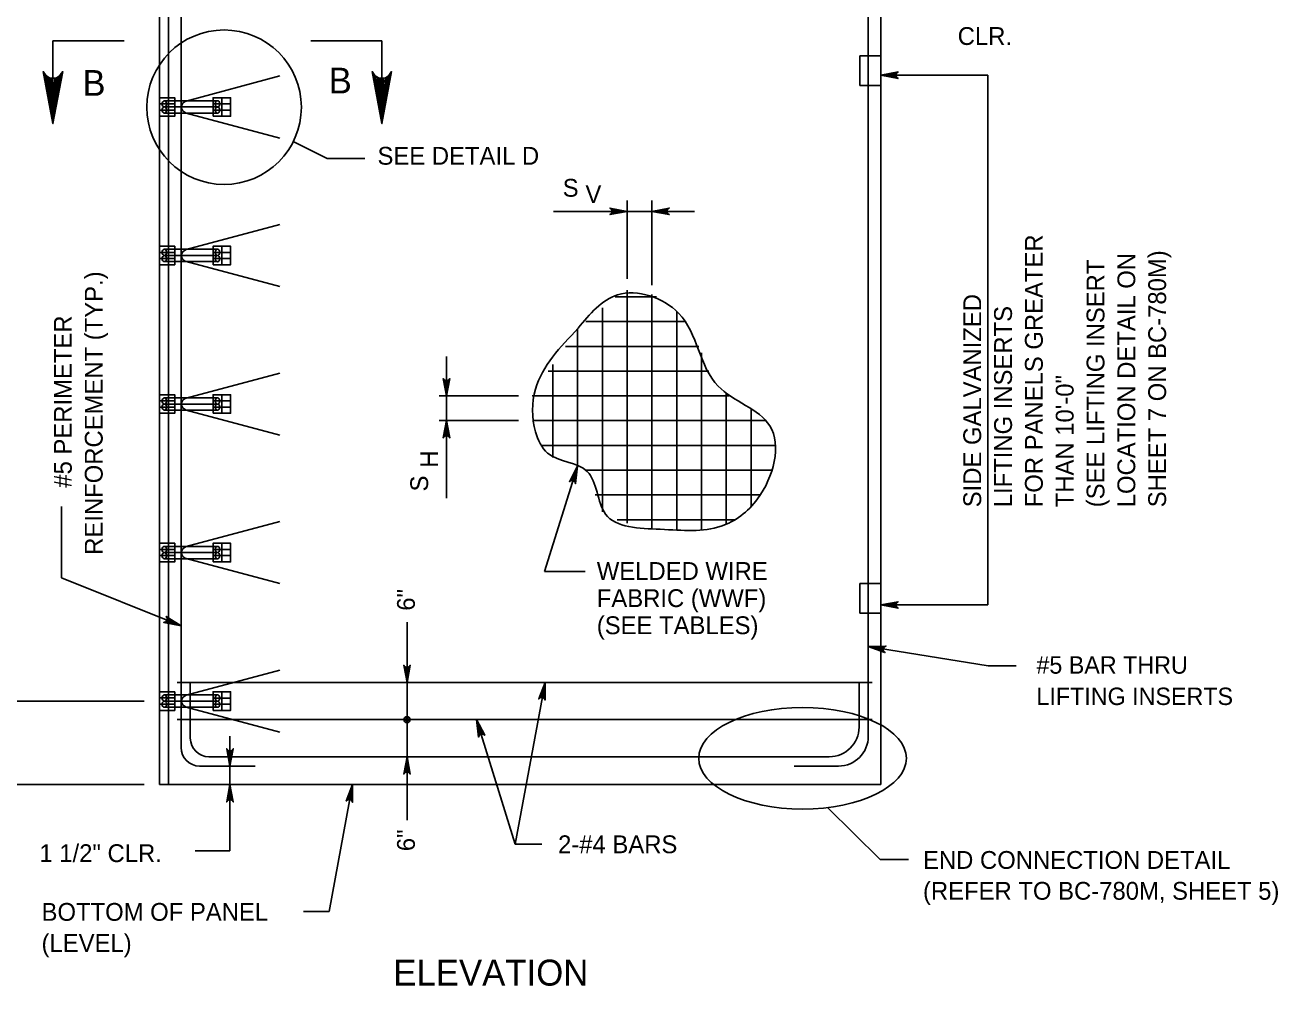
# Model space of a CAD drawing. Extents: x 3385 to 6532, y -616 to 1166.
# Drawn here: x 5875.8 to 6091.7, y 266.6 to 432.2 of the extents above; entities that cross this region are included whole.
import ezdxf

# ---------------------------------------------------------------- set-up
doc = ezdxf.new("R2010")
doc.units = 0
doc.layers.add('1', color=7, linetype='Continuous')

msp = doc.modelspace()

# ---------------------------------------------------------------- linework, layer by layer
at = {"layer": '1'}
for p, q in [((5899.03, 456.51), (5899.03, 301.32)), ((5900.59, 456.51), (5900.59, 301.32)), ((6023.26, 456.51), (6023.26, 301.32)), ((5902.72, 450.11), (5902.72, 307.72)), ((6021.13, 448.19), (6021.13, 309.64)), ((5892.92, 429.52), (5880.66, 429.52)), ((5880.66, 429.52), (5880.66, 415.25)), ((5925.07, 429.52), (5937.33, 429.52)), ((5937.33, 429.52), (5937.33, 415.25)), ((6023.26, 426.95), (6019.68, 426.95)), ((6019.68, 421.83), (6019.68, 426.95)), ((5919.73, 423.45), (5903.62, 419.13)), ((6041.73, 423.58), (6023.26, 423.58)), ((6041.73, 423.58), (6041.73, 332.29)), ((6023.26, 421.83), (6019.68, 421.83)), ((5909, 419.18), (5899.85, 419.18)), ((5909.76, 417.58), (5909.76, 419.71)), ((5909, 418.11), (5899.85, 418.11)), ((5909, 417.05), (5899.85, 417.05)), ((5903.62, 417.07), (5919.73, 412.75)), ((5909.76, 417.58), (5909.76, 416.51)), ((5927.9, 409.23), (5922.05, 412.14)), ((5934.38, 409.23), (5927.9, 409.23)), ((5979.59, 388.47), (5979.59, 402)), ((5983.85, 387.38), (5983.85, 402)), ((5966.92, 400.12), (5991.16, 400.12)), ((5919.73, 397.85), (5903.62, 393.53)), ((5909, 393.58), (5899.85, 393.58)), ((5909.76, 391.98), (5909.76, 394.11)), ((5909, 392.51), (5899.85, 392.51)), ((5909, 391.45), (5899.85, 391.45)), ((5903.62, 391.47), (5919.73, 387.16)), ((5909.76, 391.98), (5909.76, 390.91)), ((5979.59, 386.53), (5979.59, 346.37)), ((5984.64, 385.38), (5977.53, 385.38)), ((5983.85, 385.78), (5983.85, 345.49)), ((5975.32, 383.51), (5975.32, 348.34)), ((5988.12, 382.88), (5988.12, 345.11)), ((5989.71, 381.12), (5972.49, 381.12)), ((5971.05, 379.85), (5971.05, 356.21)), ((5991.94, 376.85), (5968.95, 376.85)), ((5992.38, 375.72), (5992.38, 345.19)), ((5948.45, 350.69), (5948.45, 375.09)), ((5966.79, 373.75), (5966.79, 357.7)), ((5919.73, 372.25), (5903.62, 367.93)), ((5993.67, 372.58), (5965.97, 372.58)), ((5909, 367.98), (5899.85, 367.98)), ((5909.76, 366.38), (5909.76, 368.51)), ((5947.22, 368.32), (5960.86, 368.32)), ((5997.14, 368.32), (5963.23, 368.32)), ((5996.65, 368.67), (5996.65, 346.17)), ((5909, 366.91), (5899.85, 366.91)), ((5909, 365.85), (5899.85, 365.85)), ((5903.62, 365.87), (5919.73, 361.56)), ((5909.76, 366.38), (5909.76, 365.31)), ((6000.92, 366.01), (6000.92, 349.28)), ((5947.22, 364.05), (5960.86, 364.05)), ((6003.48, 364.05), (5963.28, 364.05)), ((6005.15, 359.78), (5964.86, 359.78)), ((5971.05, 356.21), (5965.34, 338.05)), ((6004.63, 355.52), (5972.43, 355.52)), ((6002.59, 351.25), (5974.09, 351.25)), ((5882.15, 349.23), (5882.15, 336.95)), ((5919.73, 346.65), (5903.62, 342.33)), ((5998.22, 346.98), (5977.85, 346.98)), ((5909, 342.38), (5899.85, 342.38)), ((5909, 341.31), (5899.85, 341.31)), ((5909.76, 340.78), (5909.76, 342.91)), ((5909, 340.25), (5899.85, 340.25)), ((5903.62, 340.27), (5919.73, 335.96)), ((5909.76, 340.78), (5909.76, 339.71)), ((5882.15, 336.95), (5902.72, 328.68)), ((5965.34, 338.05), (5972.37, 338.05)), ((6023.26, 336), (6019.68, 336)), ((6019.68, 330.88), (6019.68, 336)), ((6023.26, 330.88), (6019.68, 330.88)), ((6041.73, 332.29), (6023.26, 332.29)), ((5941.66, 329.32), (5941.66, 295.19)), ((6041.78, 321.81), (6021.13, 325.11)), ((6046.59, 321.81), (6041.78, 321.81)), ((5919.73, 321.05), (5903.62, 316.73)), ((5902.07, 318.92), (6021.78, 318.92)), ((5904.32, 309.32), (5904.32, 318.92)), ((5909.76, 315.18), (5909.76, 317.32)), ((5960.28, 291.04), (5965.45, 318.92)), ((6019.53, 311.24), (6019.53, 318.92)), ((5870.36, 315.72), (5896.39, 315.72)), ((5909, 316.78), (5899.85, 316.78)), ((5909, 315.71), (5899.85, 315.71)), ((5909.76, 315.18), (5909.76, 314.11)), ((5909, 314.65), (5899.85, 314.65)), ((5903.62, 314.67), (5919.73, 310.36)), ((5902.07, 312.52), (6021.78, 312.52)), ((5960.28, 291.04), (5953.63, 312.52)), ((5911.15, 309.66), (5911.15, 289.91)), ((5905.92, 304.52), (5915.52, 304.52)), ((5907.52, 306.12), (6014.41, 306.12)), ((6008.33, 304.52), (6016.01, 304.52)), ((5896.39, 301.32), (5826.79, 301.32)), ((5899.03, 301.32), (6023.26, 301.32)), ((5928.22, 279.47), (5932.27, 301.32)), ((6014.11, 297.37), (6023.15, 288.4)), ((5905.13, 289.91), (5911.15, 289.91)), ((5960.28, 291.04), (5964.91, 291.04)), ((6028.06, 288.4), (6023.15, 288.4)), ((5928.22, 279.47), (5923.83, 279.47))]:
    msp.add_line(p, q, dxfattribs=at)
for points in [[(5880.66, 415.25), (5882.33, 424.2), (5882.09, 423.85), (5881.86, 423.51), (5881.56, 423.33), (5881.26, 423.15), (5880.96, 423.1), (5880.66, 423.05), (5880.36, 423.1), (5880.06, 423.15), (5879.76, 423.33), (5879.46, 423.51), (5879.22, 423.85), (5878.98, 424.2), (5880.66, 415.25), (5879.22, 423.85), (5879.46, 423.51), (5880.66, 415.25), (5879.76, 423.33), (5880.06, 423.15), (5880.66, 415.25), (5880.36, 423.1), (5880.66, 423.05), (5880.66, 415.25), (5880.96, 423.1), (5881.26, 423.15), (5880.66, 415.25), (5881.56, 423.33), (5881.86, 423.51), (5880.66, 415.25), (5882.09, 423.85)], [(5937.33, 415.25), (5935.66, 424.2), (5935.89, 423.85), (5936.13, 423.51), (5936.43, 423.33), (5936.73, 423.15), (5937.03, 423.1), (5937.33, 423.05), (5937.63, 423.1), (5937.93, 423.15), (5938.23, 423.33), (5938.53, 423.51), (5938.77, 423.85), (5939.01, 424.2), (5937.33, 415.25), (5938.77, 423.85), (5938.53, 423.51), (5937.33, 415.25), (5938.23, 423.33), (5937.93, 423.15), (5937.33, 415.25), (5937.63, 423.1), (5937.33, 423.05), (5937.33, 415.25), (5937.03, 423.1), (5936.73, 423.15), (5937.33, 415.25), (5936.43, 423.33), (5936.13, 423.51), (5937.33, 415.25), (5935.89, 423.85)], [(6023.26, 423.58), (6026.25, 423.02), (6026.02, 423.18), (6025.9, 423.38), (6025.86, 423.58), (6025.9, 423.78), (6026.02, 423.98), (6026.25, 424.14), (6023.26, 423.58), (6026.02, 423.98), (6025.9, 423.78), (6023.26, 423.58), (6025.86, 423.58), (6025.9, 423.38), (6023.26, 423.58), (6026.02, 423.18)], [(5979.59, 400.12), (5976.6, 399.56), (5976.72, 399.64), (5976.83, 399.72), (5976.89, 399.82), (5976.95, 399.92), (5976.97, 400.02), (5976.99, 400.12), (5976.97, 400.22), (5976.95, 400.32), (5976.89, 400.42), (5976.83, 400.52), (5976.72, 400.6), (5976.6, 400.68), (5979.59, 400.12), (5976.72, 400.6), (5976.83, 400.52), (5979.59, 400.12), (5976.89, 400.42), (5976.95, 400.32), (5979.59, 400.12), (5976.97, 400.22), (5976.99, 400.12), (5979.59, 400.12), (5976.97, 400.02), (5976.95, 399.92), (5979.59, 400.12), (5976.89, 399.82), (5976.83, 399.72), (5979.59, 400.12), (5976.72, 399.64)], [(5983.85, 400.12), (5986.83, 400.68), (5986.72, 400.6), (5986.6, 400.52), (5986.55, 400.42), (5986.49, 400.32), (5986.47, 400.22), (5986.45, 400.12), (5986.47, 400.02), (5986.49, 399.92), (5986.55, 399.82), (5986.6, 399.72), (5986.72, 399.64), (5986.83, 399.56), (5983.85, 400.12), (5986.72, 399.64), (5986.6, 399.72), (5983.85, 400.12), (5986.55, 399.82), (5986.49, 399.92), (5983.85, 400.12), (5986.47, 400.02), (5986.45, 400.12), (5983.85, 400.12), (5986.47, 400.22), (5986.49, 400.32), (5983.85, 400.12), (5986.55, 400.42), (5986.6, 400.52), (5983.85, 400.12), (5986.72, 400.6)], [(5948.45, 368.32), (5947.89, 371.3), (5947.97, 371.18), (5948.05, 371.07), (5948.15, 371.01), (5948.25, 370.95), (5948.35, 370.93), (5948.45, 370.92), (5948.55, 370.93), (5948.65, 370.95), (5948.75, 371.01), (5948.85, 371.07), (5948.93, 371.18), (5949.01, 371.3), (5948.45, 368.32), (5948.93, 371.18), (5948.85, 371.07), (5948.45, 368.32), (5948.75, 371.01), (5948.65, 370.95), (5948.45, 368.32), (5948.55, 370.93), (5948.45, 370.92), (5948.45, 368.32), (5948.35, 370.93), (5948.25, 370.95), (5948.45, 368.32), (5948.15, 371.01), (5948.05, 371.07), (5948.45, 368.32), (5947.97, 371.18)], [(5948.45, 364.05), (5949.01, 361.07), (5948.93, 361.18), (5948.85, 361.3), (5948.75, 361.36), (5948.65, 361.42), (5948.55, 361.43), (5948.45, 361.45), (5948.35, 361.43), (5948.25, 361.42), (5948.15, 361.36), (5948.05, 361.3), (5947.97, 361.18), (5947.89, 361.07), (5948.45, 364.05), (5947.97, 361.18), (5948.05, 361.3), (5948.45, 364.05), (5948.15, 361.36), (5948.25, 361.42), (5948.45, 364.05), (5948.35, 361.43), (5948.45, 361.45), (5948.45, 364.05), (5948.55, 361.43), (5948.65, 361.42), (5948.45, 364.05), (5948.75, 361.36), (5948.85, 361.3), (5948.45, 364.05), (5948.93, 361.18)], [(5971.05, 356.21), (5970.69, 353.2), (5970.65, 353.33), (5970.61, 353.47), (5970.53, 353.55), (5970.45, 353.64), (5970.36, 353.69), (5970.27, 353.73), (5970.17, 353.75), (5970.07, 353.76), (5969.96, 353.73), (5969.84, 353.71), (5969.73, 353.62), (5969.62, 353.53), (5971.05, 356.21), (5969.73, 353.62), (5969.84, 353.71), (5971.05, 356.21), (5969.96, 353.73), (5970.07, 353.76), (5971.05, 356.21), (5970.17, 353.75), (5970.27, 353.73), (5971.05, 356.21), (5970.36, 353.69), (5970.45, 353.64), (5971.05, 356.21), (5970.53, 353.55), (5970.61, 353.47), (5971.05, 356.21), (5970.65, 353.33)], [(6023.26, 332.29), (6026.25, 331.73), (6026.02, 331.89), (6025.9, 332.09), (6025.86, 332.29), (6025.9, 332.49), (6026.02, 332.69), (6026.25, 332.85), (6023.26, 332.29), (6026.02, 332.69), (6025.9, 332.49), (6023.26, 332.29), (6025.86, 332.29), (6025.9, 332.09), (6023.26, 332.29), (6026.02, 331.89)], [(5902.72, 328.68), (5899.75, 329.28), (5899.88, 329.31), (5900.02, 329.34), (5900.11, 329.41), (5900.2, 329.48), (5900.26, 329.57), (5900.31, 329.65), (5900.33, 329.75), (5900.35, 329.85), (5900.33, 329.97), (5900.32, 330.08), (5900.24, 330.2), (5900.16, 330.32), (5902.72, 328.68), (5900.24, 330.2), (5900.32, 330.08), (5902.72, 328.68), (5900.33, 329.97), (5900.35, 329.85), (5902.72, 328.68), (5900.33, 329.75), (5900.31, 329.65), (5902.72, 328.68), (5900.26, 329.57), (5900.2, 329.48), (5902.72, 328.68), (5900.11, 329.41), (5900.02, 329.34), (5902.72, 328.68), (5899.88, 329.31)], [(6021.13, 325.11), (6024.16, 325.19), (6024.04, 325.13), (6023.91, 325.07), (6023.84, 324.98), (6023.76, 324.89), (6023.73, 324.8), (6023.7, 324.7), (6023.7, 324.6), (6023.7, 324.5), (6023.74, 324.39), (6023.79, 324.28), (6023.89, 324.19), (6023.99, 324.09), (6021.13, 325.11), (6023.89, 324.19), (6023.79, 324.28), (6021.13, 325.11), (6023.74, 324.39), (6023.7, 324.5), (6021.13, 325.11), (6023.7, 324.6), (6023.7, 324.7), (6021.13, 325.11), (6023.73, 324.8), (6023.76, 324.89), (6021.13, 325.11), (6023.84, 324.98), (6023.91, 325.07), (6021.13, 325.11), (6024.04, 325.13)], [(5941.66, 318.92), (5941.1, 321.9), (5941.18, 321.78), (5941.26, 321.67), (5941.36, 321.61), (5941.46, 321.55), (5941.56, 321.53), (5941.66, 321.52), (5941.76, 321.53), (5941.86, 321.55), (5941.96, 321.61), (5942.06, 321.67), (5942.14, 321.78), (5942.22, 321.9), (5941.66, 318.92), (5942.14, 321.78), (5942.06, 321.67), (5941.66, 318.92), (5941.96, 321.61), (5941.86, 321.55), (5941.66, 318.92), (5941.76, 321.53), (5941.66, 321.52), (5941.66, 318.92), (5941.56, 321.53), (5941.46, 321.55), (5941.66, 318.92), (5941.36, 321.61), (5941.26, 321.67), (5941.66, 318.92), (5941.18, 321.78)], [(5965.45, 318.92), (5965.45, 315.88), (5965.4, 316.01), (5965.34, 316.14), (5965.25, 316.21), (5965.16, 316.29), (5965.07, 316.32), (5964.97, 316.36), (5964.87, 316.36), (5964.77, 316.36), (5964.66, 316.32), (5964.55, 316.28), (5964.45, 316.18), (5964.35, 316.08), (5965.45, 318.92), (5964.45, 316.18), (5964.55, 316.28), (5965.45, 318.92), (5964.66, 316.32), (5964.77, 316.36), (5965.45, 318.92), (5964.87, 316.36), (5964.97, 316.36), (5965.45, 318.92), (5965.07, 316.32), (5965.16, 316.29), (5965.45, 318.92), (5965.25, 316.21), (5965.34, 316.14), (5965.45, 318.92), (5965.4, 316.01)], [(5953.63, 312.52), (5955.04, 309.83), (5954.93, 309.92), (5954.82, 310), (5954.71, 310.03), (5954.6, 310.06), (5954.5, 310.04), (5954.4, 310.03), (5954.31, 309.99), (5954.22, 309.94), (5954.14, 309.85), (5954.06, 309.77), (5954.02, 309.63), (5953.98, 309.5), (5953.63, 312.52), (5954.02, 309.63), (5954.06, 309.77), (5953.63, 312.52), (5954.14, 309.85), (5954.22, 309.94), (5953.63, 312.52), (5954.31, 309.99), (5954.4, 310.03), (5953.63, 312.52), (5954.5, 310.04), (5954.6, 310.06), (5953.63, 312.52), (5954.71, 310.03), (5954.82, 310), (5953.63, 312.52), (5954.93, 309.92)], [(5911.15, 304.52), (5910.59, 307.5), (5910.67, 307.38), (5910.75, 307.27), (5910.85, 307.21), (5910.95, 307.15), (5911.05, 307.13), (5911.15, 307.12), (5911.25, 307.13), (5911.35, 307.15), (5911.45, 307.21), (5911.55, 307.27), (5911.63, 307.38), (5911.71, 307.5), (5911.15, 304.52), (5911.63, 307.38), (5911.55, 307.27), (5911.15, 304.52), (5911.45, 307.21), (5911.35, 307.15), (5911.15, 304.52), (5911.25, 307.13), (5911.15, 307.12), (5911.15, 304.52), (5911.05, 307.13), (5910.95, 307.15), (5911.15, 304.52), (5910.85, 307.21), (5910.75, 307.27), (5911.15, 304.52), (5910.67, 307.38)], [(5941.66, 306.12), (5942.22, 303.13), (5942.14, 303.25), (5942.06, 303.36), (5941.96, 303.42), (5941.86, 303.48), (5941.76, 303.5), (5941.66, 303.52), (5941.56, 303.5), (5941.46, 303.48), (5941.36, 303.42), (5941.26, 303.36), (5941.18, 303.25), (5941.1, 303.13), (5941.66, 306.12), (5941.18, 303.25), (5941.26, 303.36), (5941.66, 306.12), (5941.36, 303.42), (5941.46, 303.48), (5941.66, 306.12), (5941.56, 303.5), (5941.66, 303.52), (5941.66, 306.12), (5941.76, 303.5), (5941.86, 303.48), (5941.66, 306.12), (5941.96, 303.42), (5942.06, 303.36), (5941.66, 306.12), (5942.14, 303.25)], [(5911.15, 301.32), (5911.71, 298.33), (5911.63, 298.45), (5911.55, 298.56), (5911.45, 298.62), (5911.35, 298.68), (5911.25, 298.7), (5911.15, 298.72), (5911.05, 298.7), (5910.95, 298.68), (5910.85, 298.62), (5910.75, 298.56), (5910.67, 298.45), (5910.59, 298.33), (5911.15, 301.32), (5910.67, 298.45), (5910.75, 298.56), (5911.15, 301.32), (5910.85, 298.62), (5910.95, 298.68), (5911.15, 301.32), (5911.05, 298.7), (5911.15, 298.72), (5911.15, 301.32), (5911.25, 298.7), (5911.35, 298.68), (5911.15, 301.32), (5911.45, 298.62), (5911.55, 298.56), (5911.15, 301.32), (5911.63, 298.45)], [(5932.27, 301.32), (5932.28, 298.28), (5932.22, 298.41), (5932.16, 298.54), (5932.07, 298.61), (5931.99, 298.69), (5931.89, 298.72), (5931.8, 298.76), (5931.7, 298.76), (5931.59, 298.76), (5931.48, 298.72), (5931.38, 298.68), (5931.28, 298.58), (5931.18, 298.48), (5932.27, 301.32), (5931.28, 298.58), (5931.38, 298.68), (5932.27, 301.32), (5931.48, 298.72), (5931.59, 298.76), (5932.27, 301.32), (5931.7, 298.76), (5931.8, 298.76), (5932.27, 301.32), (5931.89, 298.72), (5931.99, 298.69), (5932.27, 301.32), (5932.07, 298.61), (5932.16, 298.54), (5932.27, 301.32), (5932.22, 298.41)]]:
    msp.add_lwpolyline(points, dxfattribs=at)
for points in [[(5899.03, 417.58), (5901.65, 417.58), (5901.65, 419.71), (5899.03, 419.71)], [(5908.25, 417.58), (5911.27, 417.58), (5911.27, 419.71), (5908.25, 419.71)], [(5899.03, 416.51), (5901.65, 416.51), (5901.65, 418.64), (5899.03, 418.64)], [(5908.25, 416.51), (5911.27, 416.51), (5911.27, 418.64), (5908.25, 418.64)], [(5899.03, 391.98), (5901.65, 391.98), (5901.65, 394.11), (5899.03, 394.11)], [(5899.03, 390.91), (5901.65, 390.91), (5901.65, 393.05), (5899.03, 393.05)], [(5908.25, 391.98), (5911.27, 391.98), (5911.27, 394.11), (5908.25, 394.11)], [(5908.25, 390.91), (5911.27, 390.91), (5911.27, 393.04), (5908.25, 393.04)], [(5899.03, 366.38), (5901.65, 366.38), (5901.65, 368.51), (5899.03, 368.51)], [(5899.03, 365.31), (5901.65, 365.31), (5901.65, 367.45), (5899.03, 367.45)], [(5908.25, 366.38), (5911.27, 366.38), (5911.27, 368.51), (5908.25, 368.51)], [(5908.25, 365.31), (5911.27, 365.31), (5911.27, 367.44), (5908.25, 367.44)], [(5899.03, 340.78), (5901.65, 340.78), (5901.65, 342.91), (5899.03, 342.91)], [(5899.03, 339.71), (5901.65, 339.71), (5901.65, 341.85), (5899.03, 341.85)], [(5908.25, 340.78), (5911.27, 340.78), (5911.27, 342.91), (5908.25, 342.91)], [(5908.25, 339.71), (5911.27, 339.71), (5911.27, 341.84), (5908.25, 341.84)], [(5899.03, 315.18), (5901.65, 315.18), (5901.65, 317.31), (5899.03, 317.31)], [(5908.25, 315.18), (5911.27, 315.18), (5911.27, 317.32), (5908.25, 317.32)], [(5899.03, 314.11), (5901.65, 314.11), (5901.65, 316.25), (5899.03, 316.25)], [(5908.25, 314.11), (5911.27, 314.11), (5911.27, 316.24), (5908.25, 316.24)]]:
    msp.add_lwpolyline(points, close=True, dxfattribs=at)
for centre, radius in [((5910.14, 418.07), 13.31), ((5941.66, 312.52), 0.533), ((5941.66, 312.52), 0.267)]:
    msp.add_circle(centre, radius, dxfattribs=at)
for centre, radius, start, end in [((5903.89, 418.1), 1.07, 105, 255), ((5903.89, 392.5), 1.07, 105, 255), ((5903.89, 366.9), 1.07, 105, 255), ((5903.89, 341.3), 1.07, 105, 255), ((5903.89, 315.7), 1.07, 105, 255), ((6014.41, 311.24), 5.12, 270, 360), ((5907.52, 309.32), 3.2, 180, 270), ((6016.01, 309.64), 5.12, 270, 360), ((5905.92, 307.72), 3.2, 180, 270)]:
    msp.add_arc(centre, radius, start, end, dxfattribs=at)
for centre, major_axis, ratio in [((5899.85, 418.64), (0, 0.534), 0.741868), ((5909, 418.65), (0, 0.534), 0.741868), ((5899.85, 417.58), (0, 0.531), 0.745444), ((5909, 417.57), (0, 0.534), 0.741868), ((5899.85, 393.04), (0, 0.534), 0.741868), ((5909, 393.05), (0, 0.534), 0.741868), ((5899.85, 391.98), (0, 0.531), 0.745444), ((5909, 391.98), (0, 0.534), 0.741868), ((5899.85, 367.44), (0, 0.534), 0.741868), ((5909, 367.45), (0, 0.534), 0.741868), ((5899.85, 366.38), (0, 0.531), 0.745444), ((5909, 366.38), (0, 0.534), 0.741868), ((5899.85, 341.84), (0, 0.534), 0.741868), ((5899.85, 340.78), (0, 0.531), 0.745444), ((5909, 341.85), (0, 0.534), 0.741868), ((5909, 340.78), (0, 0.534), 0.741868), ((5899.85, 316.24), (0, 0.534), 0.741868), ((5899.85, 315.18), (0, 0.531), 0.745444), ((5909, 316.25), (0, 0.534), 0.741868), ((5909, 315.18), (0, 0.534), 0.741868), ((6009.8, 305.86), (17.89, 0), 0.489021)]:
    msp.add_ellipse(centre, major_axis=major_axis, ratio=ratio, dxfattribs=at)
msp.add_spline([(5971.13, 379.96), (5963.79, 369.47), (5963.79, 362.12), (5965.88, 358.45), (5972.7, 355.3), (5975.85, 347.95), (5985.28, 345.33), (5995.77, 345.85), (6002.06, 350.58), (6004.16, 363.17), (5995.25, 369.99), (5988.43, 382.59), (5977.94, 385.73), (5971.13, 379.96)], degree=3, dxfattribs=at)

# ---------------------------------------------------------------- texts
for s, height, p in [('CLR.', 3.072, (6036.53, 428.8)), ('B', 4.45, (5885.74, 420.03)), ('B', 4.45, (5928.17, 420.44)), ('SEE DETAIL D', 3.072, (5936.57, 408.16)), ('S', 3.07, (5968.48, 402.64)), ('V', 3.07, (5972.4, 401.54)), ('WELDED WIRE', 3.072, (5974.35, 336.6)), ('FABRIC (WWF)', 3.072, (5974.35, 331.92)), ('(SEE TABLES)', 3.072, (5974.35, 327.25)), ('#5 BAR THRU', 3, (6050.09, 320.44)), ('LIFTING INSERTS', 3, (6050.09, 315.04)), ('2-#4 BARS', 3.072, (5967.68, 289.5)), ('1 1/2" CLR.', 3.072, (5878.32, 287.97)), ('END CONNECTION DETAIL', 3.072, (6030.55, 286.8)), ('(REFER TO BC-780M, SHEET 5)', 3.072, (6030.55, 281.48)), ('BOTTOM OF PANEL', 3.072, (5878.69, 277.85)), ('(LEVEL)', 3.072, (5878.69, 272.48)), ('ELEVATION', 4.477, (5939.29, 266.68))]:
    msp.add_text(s, height=height, dxfattribs=at).set_placement(p)
for s, height, p in [('FOR PANELS GREATER', 3.072, (6051.19, 349.12)), ('SHEET 7 ON BC-780M)', 3.072, (6072.43, 349.12)), ('(SEE LIFTING INSERT', 3.072, (6061.81, 349.12)), ('LOCATION DETAIL ON', 3.072, (6067.12, 349.12)), ('REINFORCEMENT (TYP.)', 3.072, (5889.22, 340.93)), ('SIDE GALVANIZED', 3.072, (6040.57, 349.12)), ('LIFTING INSERTS', 3.072, (6045.88, 349.12)), ('#5 PERIMETER', 3.072, (5883.9, 352.5)), ('THAN 10\'-0"', 3.072, (6056.5, 349.12)), ('H', 3.07, (5947.01, 355.94)), ('S', 3.07, (5945.29, 351.85)), ('6"', 3.072, (5943.01, 331.29)), ('6"', 3.072, (5943.01, 289.85))]:
    msp.add_text(s, height=height, rotation=90, dxfattribs=at).set_placement(p)

doc.saveas('drawing.dxf')
